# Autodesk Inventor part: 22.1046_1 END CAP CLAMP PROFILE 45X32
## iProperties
Created: 2007-01
Part Number: 22.1046_1 END CAP CLAMP PROFILE 45X32
Document SubType Name: Modeling
Designer: Andy Moles
Material: ABS Plastic
Density: 1.06 g/cm^3
Mass: 4.9319 g
Surface Area: 37.9211 cm^2
Volume: 4.65274 cm^3
Author: Andy Moles
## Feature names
1. Extrusion1
2. Fillet1
3. Fillet2
4. Extrusion2
5. Extrusion3
6. Fillet3
7. Extrusion4
8. Fillet4
